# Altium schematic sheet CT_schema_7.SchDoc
size 267 x 267 mm
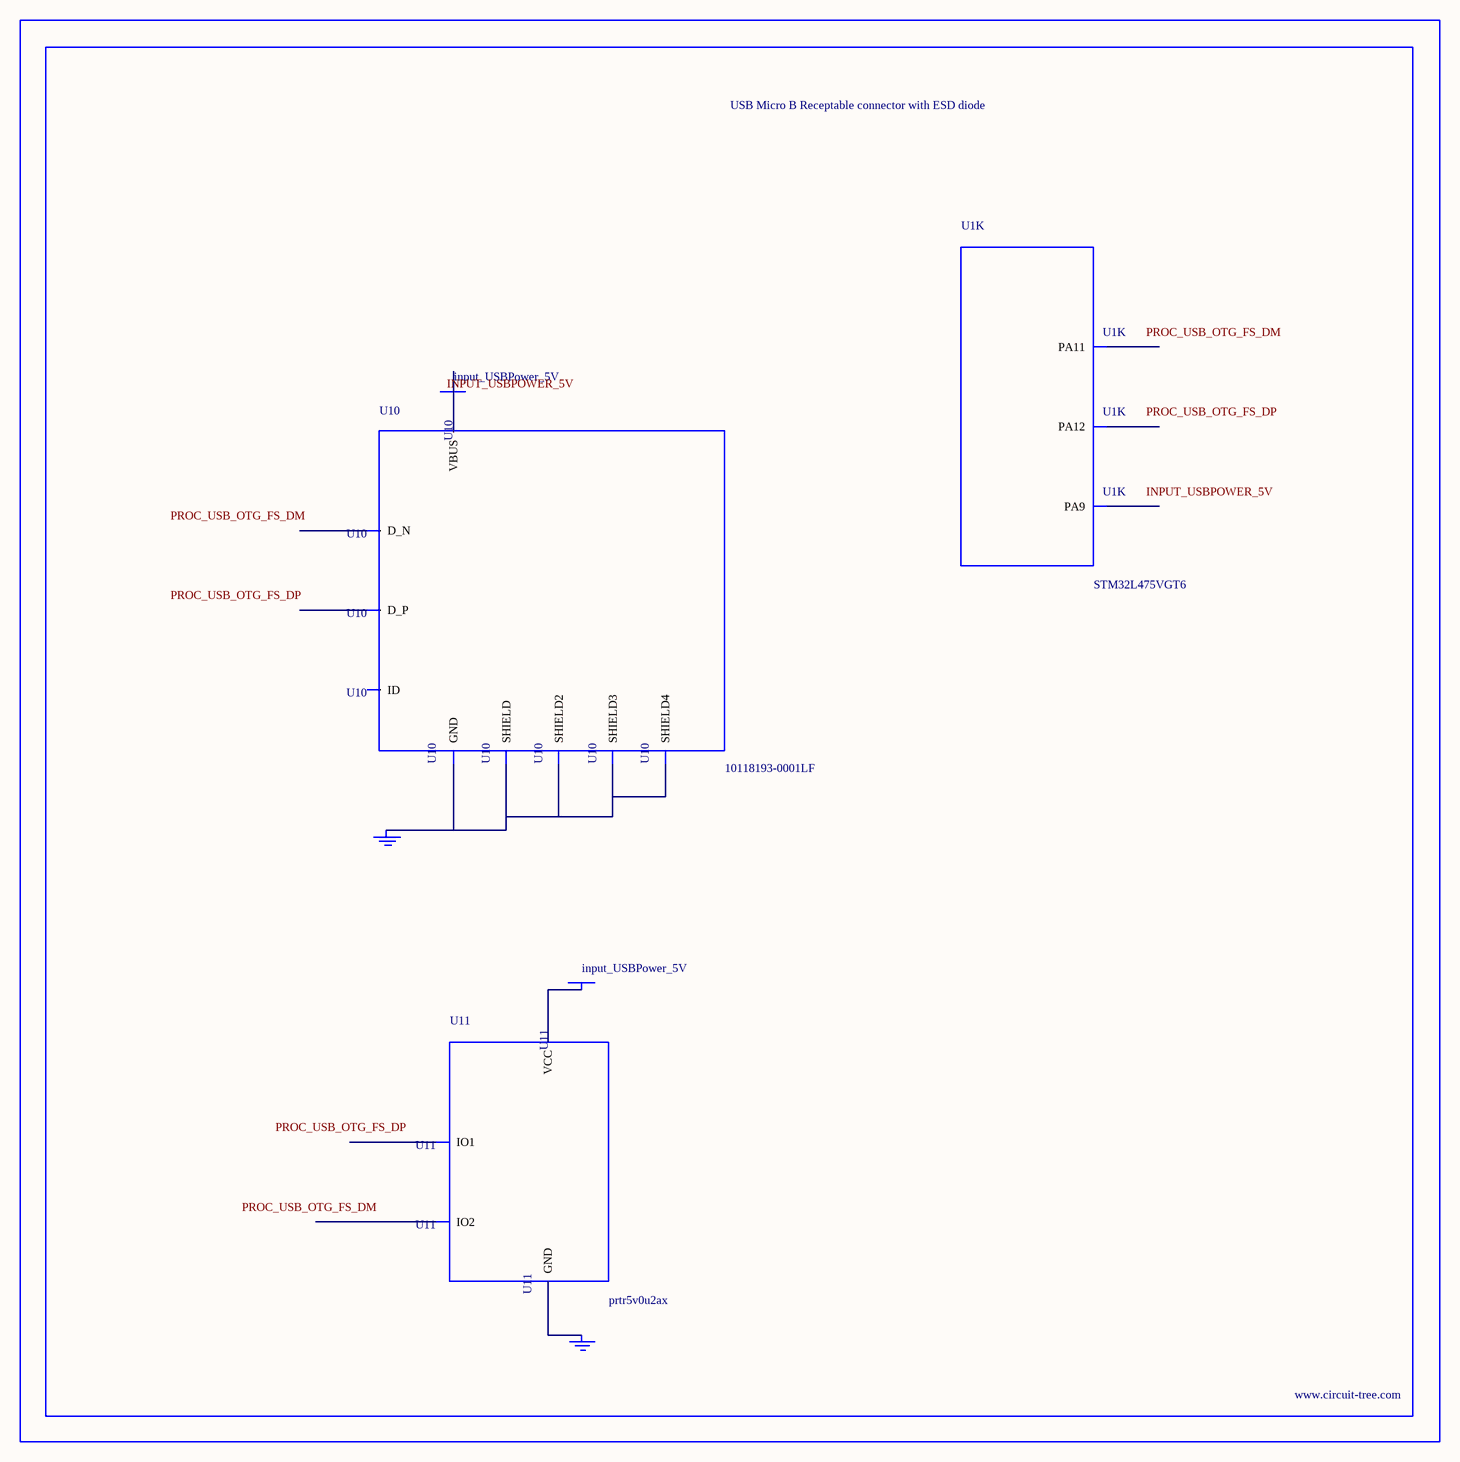
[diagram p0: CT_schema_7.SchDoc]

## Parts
BORDER6  (no value)
GND_INSTANCE_6_0  (no value)
GND_INSTANCE_6_1  (no value)
POWER_INSTANCE_6_0  input_USBPower_5V
POWER_INSTANCE_6_1  input_USBPower_5V
U1  STM32L475VGT6  [LQFP100]  (part K of 11)
U10  10118193-0001LF  [FCI_10118193-0001LF]
U11  prtr5v0u2ax  [SOT143B]

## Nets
NetGND_INSTANCE_6_0_0: GND_INSTANCE_6_0.0(GND) U10.5(GND) U10.6(SHIELD) U10.7(SHIELD2) U10.8(SHIELD3) U10.9(SHIELD4)
NetGND_INSTANCE_6_1_0: GND_INSTANCE_6_1.0(GND) U11.1(GND)
NetPOWER_INSTANCE_6_0_0: POWER_INSTANCE_6_0.0(PWR) U10.1(VBUS)
NetPOWER_INSTANCE_6_1_0: POWER_INSTANCE_6_1.0(PWR) U11.4(VCC)

Not connected (* = marked no-connect by the designer): U1 68(PA9) 70(PA11) 71(PA12); U10 2(D_N) 3(D_P) 4(ID); U11 2(IO1) 3(IO2)

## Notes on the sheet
- Labels drawn without touching a wire or pin: INPUT_USBPOWER_5V, PROC_USB_OTG_FS_DM, PROC_USB_OTG_FS_DP

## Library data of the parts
BORDER6 = BORDER_PAGE6
GND_INSTANCE_6_0 GND_INSTANCE_6_1 = GND
POWER_INSTANCE_6_0 POWER_INSTANCE_6_1 = PWR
